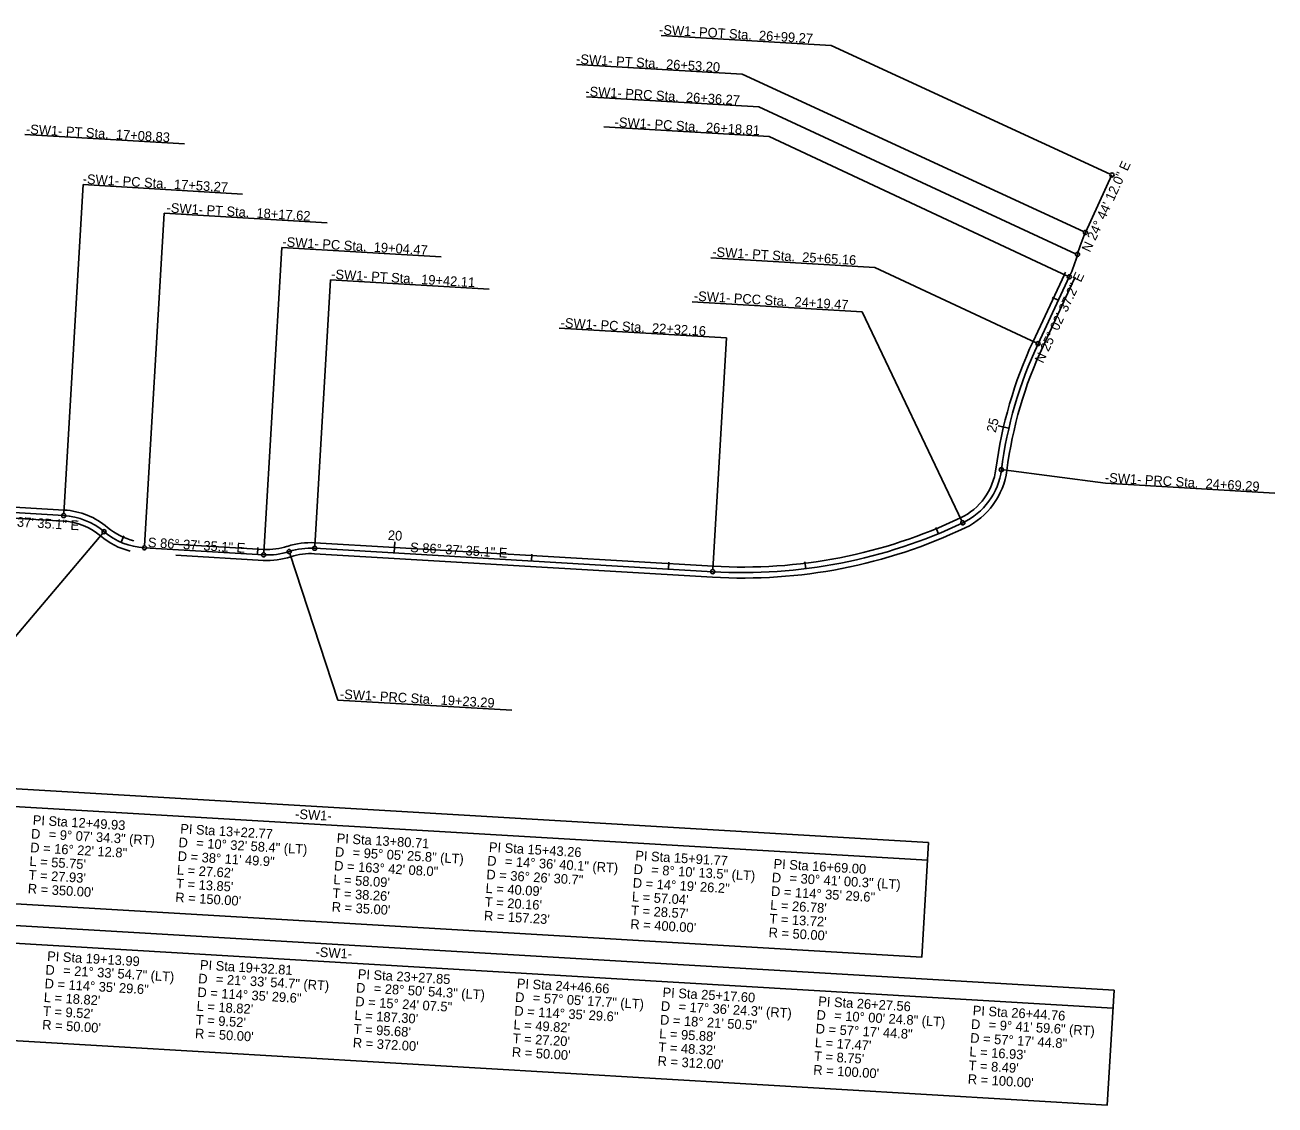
# Model space of a CAD drawing. Extents: x 2011926 to 2013370, y 444604 to 445429.
# Drawn here: x 2012461 to 2013370, y 444604 to 445390 of the extents above; entities that cross this region are included whole.
import ezdxf

# ---------------------------------------------------------------- set-up
doc = ezdxf.new("R2010")
doc.units = 0
for name, color, linetype in [('CTL Secondary Horizontal and Vertical CELL', 7, 'Continuous'), ('Exist Structure Minor Drop Inlet Cogo Number', 7, 'Continuous'), ('Exist Structure Minor Pipes RCP 18 Inch', 7, 'Continuous'), ('Exist Structure Minor Pipes RCP 18 Inch Cogo Point CELL', 7, 'Continuous'), ('Exist Structure Minor Pipes RCP 24 Inch Cogo Point CELL', 7, 'Continuous'), ('Exist Structure Minor Pipes RCP 36 Inch', 7, 'Continuous'), ('Exist Utilities Sanitary Sewer UG Line', 7, 'Continuous'), ('Exist Utilities Sanitary Sewer UG Line Cogo Number', 7, 'Continuous')]:
    doc.layers.add(name, color=color, linetype=linetype)

msp = doc.modelspace()

# ---------------------------------------------------------------- linework, layer by layer
at = {"layer": 'CTL Secondary Horizontal and Vertical CELL'}
for p, q in [((2013194.49, 445159.8), (2013217.2, 445208.4)), ((2013201.74, 445156.41), (2013224.44, 445205.01)), ((2012445.24, 445039.69), (2012489.6, 445037.07)), ((2012444.77, 445031.7), (2012489.13, 445029.09)), ((2012568.88, 445012.36), (2012635.02, 445008.47)), ((2012672.12, 445013.29), (2012961.67, 444996.22)), ((2012570.99, 445004.23), (2012634.55, 445000.48)), ((2012671.65, 445005.3), (2012961.2, 444988.24))]:
    msp.add_line(p, q, dxfattribs=at)
for centre, radius, start, end in [((2013130.22, 445249.04), 96, 334.95634, 336.07088), ((2013130.22, 445249.04), 104, 334.95634, 335.91649), ((2013480.78, 445026.04), 316, 154.95634, 172.56311), ((2013480.78, 445026.04), 308, 154.95634, 172.56311), ((2013121.83, 445072.89), 46, 295.47485, 352.56311), ((2013121.83, 445072.89), 54, 295.47485, 352.56311), ((2012486.42, 444983.17), 54, 49.75653, 86.62643), ((2012486.42, 444983.17), 54, 49.75653, 86.62643), ((2012486.42, 444983.17), 46, 49.75653, 86.62643), ((2012486.42, 444983.17), 46, 49.75653, 86.62643), ((2012551.03, 445059.5), 46, 229.75653, 256.57927), ((2012983.33, 445363.58), 376, 266.62643, 295.47485), ((2012983.33, 445363.58), 368, 266.62643, 295.47485), ((2012551.03, 445059.5), 54, 229.75653, 255.68879), ((2012637.72, 445054.39), 46, 266.62643, 288.19161), ((2012637.72, 445054.39), 46, 266.62643, 288.19161), ((2012668.94, 444959.38), 54, 86.62643, 108.19161), ((2012668.94, 444959.38), 54, 86.62643, 108.19161), ((2012637.72, 445054.39), 54, 266.62643, 288.19161), ((2012637.72, 445054.39), 54, 266.62643, 288.19161), ((2012668.94, 444959.38), 46, 86.62643, 108.19161), ((2012668.94, 444959.38), 46, 86.62643, 108.19161)]:
    msp.add_arc(centre, radius, start, end, dxfattribs=at)
at = {"layer": 'Exist Structure Minor Drop Inlet Cogo Number'}
for p, q in [((2013232.55, 445239), (2013251.83, 445280.84)), ((2013232.55, 445239), (2013251.83, 445280.84)), ((2013198.11, 445158.11), (2013220.82, 445206.71)), ((2013198.11, 445158.11), (2013220.82, 445206.71)), ((2012445, 445035.69), (2012489.36, 445033.08)), ((2012445, 445035.69), (2012489.36, 445033.08)), ((2012548.08, 445009.58), (2012634.78, 445004.47)), ((2012548.08, 445009.58), (2012634.78, 445004.47)), ((2012671.89, 445009.3), (2012961.44, 444992.23)), ((2012671.89, 445009.3), (2012961.44, 444992.23))]:
    msp.add_line(p, q, dxfattribs=at)
for centre, radius, start, end in [((2013323.37, 445197.15), 100, 155.26333, 164.96323), ((2013323.37, 445197.15), 100, 155.26333, 164.96323), ((2013130.22, 445249.04), 100, 334.95634, 344.96323), ((2013130.22, 445249.04), 100, 334.95634, 344.96323), ((2013480.78, 445026.04), 312, 154.95634, 172.56311), ((2013480.78, 445026.04), 312, 154.95634, 172.56311), ((2013121.83, 445072.89), 50, 295.47485, 352.56311), ((2013121.83, 445072.89), 50, 295.47485, 352.56311), ((2012486.42, 444983.17), 50, 49.75653, 86.62643), ((2012486.42, 444983.17), 50, 49.75653, 86.62643), ((2012983.33, 445363.58), 372, 266.62643, 295.47485), ((2012983.33, 445363.58), 372, 266.62643, 295.47485), ((2012551.03, 445059.5), 50, 229.75653, 266.62643), ((2012551.03, 445059.5), 50, 229.75653, 266.62643), ((2012637.72, 445054.39), 50, 266.62643, 288.19161), ((2012637.72, 445054.39), 50, 266.62643, 288.19161), ((2012668.94, 444959.38), 50, 86.62643, 108.19161), ((2012668.94, 444959.38), 50, 86.62643, 108.19161)]:
    msp.add_arc(centre, radius, start, end, dxfattribs=at)
at = {"layer": 'Exist Structure Minor Pipes RCP 18 Inch'}
for p, q in [((2013176.87, 445096.63), (2013169.08, 445098.44)), ((2012729.68, 445005.89), (2012730.15, 445013.88))]:
    msp.add_line(p, q, dxfattribs=at)
at = {"layer": 'Exist Structure Minor Pipes RCP 24 Inch Cogo Point CELL'}
for p, q in [((2013212.86, 445189.67), (2013208.33, 445191.79)), ((2013125.55, 445019.84), (2013123.63, 445024.46)), ((2012531.03, 445013.67), (2012533.03, 445018.25)), ((2012630.32, 445004.74), (2012630.61, 445009.73)), ((2012829.5, 445000.01), (2012829.8, 445005)), ((2012929.33, 444994.12), (2012929.62, 444999.11)), ((2013029.14, 444994.42), (2013028.53, 444999.38))]:
    msp.add_line(p, q, dxfattribs=at)
at = {"layer": 'Exist Utilities Sanitary Sewer UG Line'}
for p, q in [((2012235.82, 444834.24), (2013117.6, 444782.26)), ((2012135.32, 444740.69), (2013252.58, 444674.83))]:
    msp.add_line(p, q, dxfattribs=at)
for points in [[(2012236.58, 444847.2), (2013118.36, 444795.22), (2013113.44, 444711.71), (2012231.66, 444763.68)], [(2012136.08, 444753.64), (2013253.34, 444687.78), (2013248.42, 444604.27), (2012131.16, 444670.13)]]:
    msp.add_lwpolyline(points, close=True, dxfattribs=at)
at = {"layer": 'Exist Utilities Sanitary Sewer UG Line Cogo Number'}
for p, q in [((2013047.63, 445374.92), (2012923.97, 445382.21)), ((2013250.47, 445281.47), (2013047.63, 445374.92)), ((2012982.78, 445354.07), (2012862.25, 445361.17)), ((2013231.19, 445239.62), (2012982.78, 445354.07)), ((2012995.08, 445330.29), (2012869.59, 445337.68)), ((2013225.35, 445223.48), (2012995.08, 445330.29)), ((2013002.5, 445308.71), (2012882.17, 445315.81)), ((2012577.19, 445303.38), (2012461.18, 445310.22)), ((2013219.46, 445207.34), (2013002.5, 445308.71)), ((2012489.45, 445034.58), (2012503.55, 445273.8)), ((2012619.46, 445266.96), (2012503.55, 445273.8)), ((2012548.17, 445011.08), (2012562.44, 445253.06)), ((2012681.07, 445246.07), (2012562.44, 445253.06)), ((2012634.87, 445005.97), (2012647.96, 445228.01)), ((2012763.9, 445221.17), (2012647.96, 445228.01)), ((2013079.29, 445213.63), (2012960.01, 445220.66)), ((2013196.75, 445158.74), (2013079.29, 445213.63)), ((2012671.97, 445010.79), (2012683.4, 445204.62)), ((2012798.84, 445197.81), (2012683.4, 445204.62)), ((2013070.18, 445181.3), (2012946.52, 445188.59)), ((2013142.69, 445029.11), (2013070.18, 445181.3)), ((2012971.46, 445162.29), (2012849.69, 445169.47)), ((2012961.53, 444993.73), (2012971.46, 445162.29)), ((2013172.89, 445066.22), (2013247.07, 445056.54)), ((2013370.43, 445049.27), (2013247.07, 445056.54)), ((2012429.9, 444916.39), (2012517.75, 445020.19)), ((2012688.83, 444898.88), (2012653.8, 445005.46)), ((2012815.34, 444891.42), (2012688.83, 444898.88))]:
    msp.add_line(p, q, dxfattribs=at)
for centre in [(2013251.83, 445280.84), (2013232.55, 445239), (2013226.8, 445223.1), (2013220.82, 445206.71), (2013198.11, 445158.11), (2013171.4, 445066.42), (2012489.36, 445033.08), (2013143.33, 445027.75), (2012518.72, 445021.33), (2012548.08, 445009.58), (2012634.78, 445004.47), (2012653.33, 445006.88), (2012671.89, 445009.3), (2012961.44, 444992.23)]:
    msp.add_circle(centre, 1.5, dxfattribs=at)

# ---------------------------------------------------------------- texts
at = {"layer": 'Exist Structure Minor Pipes RCP 18 Inch Cogo Point CELL'}
for s, rotation, p in [('25', 76.9227, (2013167.3, 445093.02)), ('20', 356.62643, (2012724.99, 445015.38))]:
    msp.add_text(s, height=7, rotation=rotation, dxfattribs=at).set_placement(p)
at = {"layer": 'Exist Structure Minor Pipes RCP 36 Inch'}
for s, rotation, p in [('N 24%%d 44\' 12.0" E', 65.26333, (2013235.82, 445224.12)), ('N 25%%d 02\' 37.2" E', 64.95634, (2013201.69, 445143.38)), ('S 86%%d 37\' 35.1" E', 356.62643, (2012429.63, 445026.55)), ('S 86%%d 37\' 35.1" E', 356.62643, (2012550.44, 445010.14)), ('S 86%%d 37\' 35.1" E', 356.62643, (2012741.19, 445006.57))]:
    msp.add_text(s, height=7, rotation=rotation, dxfattribs=at).set_placement(p)
at = {"layer": 'Exist Utilities Sanitary Sewer UG Line'}
for s, p in [('PI Sta 12+49.93', (2012466.69, 444808.17)), ('-SW1-', (2012657.54, 444812.6)), ('PI Sta 13+22.77', (2012573.98, 444801.85)), ('D', (2012465.43, 444798.22)), ('= 9%%d 07\' 34.3" (RT)', (2012478.28, 444797.76)), ('D', (2012572.72, 444791.91)), ('= 10%%d 32\' 58.4" (LT)', (2012585.57, 444791.45)), ('PI Sta 13+80.71', (2012687.76, 444794.92)), ('D = 16%%d 22\' 12.8"', (2012464.84, 444788.24)), ('D = 38%%d 11\' 49.9"', (2012572.13, 444781.92)), ('D', (2012686.5, 444784.98)), ('= 95%%d 05\' 25.8" (LT)', (2012699.34, 444784.52)), ('PI Sta 15+43.26', (2012798.5, 444788.5)), ('PI Sta 15+91.77', (2012904.97, 444782.36)), ("L = 55.75'", (2012464.26, 444778.26)), ("L = 27.62'", (2012571.54, 444771.94)), ('D = 163%%d 42\' 08.0"', (2012685.91, 444775)), ('D', (2012797.24, 444778.56)), ('= 14%%d 36\' 40.1" (RT)', (2012810.09, 444778.1)), ('D', (2012903.71, 444772.42)), ('= 8%%d 10\' 13.5" (LT)', (2012916.55, 444771.96)), ('PI Sta 16+69.00', (2013005.54, 444776.32)), ("T = 27.93'", (2012463.67, 444768.27)), ("L = 58.09'", (2012685.32, 444765.01)), ('D = 36%%d 26\' 30.7"', (2012796.65, 444768.58)), ('D = 14%%d 19\' 26.2"', (2012903.12, 444762.44)), ('D', (2013004.28, 444766.37)), ('= 30%%d 41\' 00.3" (LT)', (2013017.13, 444765.91)), ("R = 350.00'", (2012463.08, 444758.29)), ("T = 13.85'", (2012570.96, 444761.96)), ("T = 38.26'", (2012684.73, 444755.03)), ("L = 40.09'", (2012796.06, 444758.59)), ('D = 114%%d 35\' 29.6"', (2013003.69, 444756.39)), ("R = 150.00'", (2012570.37, 444751.98)), ("R = 35.00'", (2012684.14, 444745.05)), ("T = 20.16'", (2012795.48, 444748.61)), ("L = 57.04'", (2012902.53, 444752.45)), ("L = 26.78'", (2013003.11, 444746.41)), ("R = 157.23'", (2012794.89, 444738.63)), ("T = 28.57'", (2012901.94, 444742.47)), ("T = 13.72'", (2013002.52, 444736.43)), ("R = 400.00'", (2012901.36, 444732.49)), ("R = 50.00'", (2013001.93, 444726.44)), ('PI Sta 19+13.99', (2012477.15, 444709.16)), ('-SW1-', (2012672.33, 444712.25)), ('D', (2012475.89, 444699.22)), ('PI Sta 19+32.81', (2012588.3, 444702.82)), ('= 21%%d 33\' 54.7" (LT)', (2012488.74, 444698.76)), ('D', (2012587.04, 444692.88)), ('= 21%%d 33\' 54.7" (RT)', (2012599.88, 444692.42)), ('PI Sta 23+27.85', (2012703.12, 444696.12)), ('D = 114%%d 35\' 29.6"', (2012475.3, 444689.24)), ('D = 114%%d 35\' 29.6"', (2012586.45, 444682.9)), ('D', (2012701.86, 444686.17)), ('= 28%%d 50\' 54.3" (LT)', (2012714.7, 444685.71)), ('PI Sta 24+46.66', (2012818.81, 444689.3)), ('PI Sta 25+17.60', (2012924.81, 444682.82)), ("L = 18.82'", (2012474.72, 444679.25)), ("L = 18.82'", (2012585.86, 444672.91)), ('D = 15%%d 24\' 07.5"', (2012701.27, 444676.19)), ('D', (2012817.54, 444679.36)), ('= 57%%d 05\' 17.7" (LT)', (2012830.39, 444678.9)), ('D', (2012923.55, 444672.88)), ('= 17%%d 36\' 24.3" (RT)', (2012936.39, 444672.42)), ('PI Sta 26+27.56', (2013038.04, 444676.34)), ("T = 9.52'", (2012474.13, 444669.27)), ("T = 9.52'", (2012585.27, 444662.93)), ("L = 187.30'", (2012700.68, 444666.21)), ('D = 114%%d 35\' 29.6"', (2012816.96, 444669.38)), ('D = 18%%d 21\' 50.5"', (2012922.96, 444662.9)), ('D', (2013036.78, 444666.4)), ('= 10%%d 00\' 24.8" (LT)', (2013049.62, 444665.94)), ('PI Sta 26+44.76', (2013150.42, 444669.62)), ("R = 50.00'", (2012473.54, 444659.29)), ("T = 95.68'", (2012700.09, 444656.23)), ("L = 49.82'", (2012816.37, 444659.39)), ('D = 57%%d 17\' 44.8"', (2013036.19, 444656.42)), ('D', (2013149.16, 444659.68)), ('= 9%%d 41\' 59.6" (RT)', (2013162, 444659.22)), ("R = 50.00'", (2012584.69, 444652.95)), ("R = 372.00'", (2012699.5, 444646.24)), ("T = 27.20'", (2012815.78, 444649.41)), ("L = 95.88'", (2012922.37, 444652.91)), ("L = 17.47'", (2013035.6, 444646.43)), ('D = 57%%d 17\' 44.8"', (2013148.57, 444649.69)), ("R = 50.00'", (2012815.19, 444639.43)), ("T = 48.32'", (2012921.78, 444642.93)), ("T = 8.75'", (2013035.01, 444636.45)), ("L = 16.93'", (2013147.98, 444639.71)), ("R = 312.00'", (2012921.2, 444632.95)), ("R = 100.00'", (2013034.43, 444626.47)), ("T = 8.49'", (2013147.39, 444629.73)), ("R = 100.00'", (2013146.8, 444619.75))]:
    msp.add_text(s, height=7, rotation=356.62643, dxfattribs=at).set_placement(p)
at = {"layer": 'Exist Utilities Sanitary Sewer UG Line Cogo Number'}
for s, p in [('-SW1- POT Sta.  26+99.27', (2012922.24, 445383.15)), ('-SW1- PT Sta.  26+53.20', (2012861.92, 445361.86)), ('-SW1- PRC Sta.  26+36.27', (2012868.6, 445338.33)), ('-SW1- PT Sta.  17+08.83', (2012461.73, 445310.8)), ('-SW1- PC Sta.  26+18.81', (2012889.9, 445315.98)), ('-SW1- PC Sta.  17+53.27', (2012502.97, 445274.57)), ('-SW1- PT Sta.  18+17.62', (2012563.99, 445253.63)), ('-SW1- PC Sta.  19+04.47', (2012648.24, 445228.84)), ('-SW1- PT Sta.  25+65.16', (2012960.94, 445221.52)), ('-SW1- PT Sta.  19+42.11', (2012683.77, 445205.32)), ('-SW1- PCC Sta.  24+19.47', (2012947.55, 445189.46)), ('-SW1- PC Sta.  22+32.16', (2012850.63, 445169.99)), ('-SW1- PRC Sta.  24+69.29', (2013246.56, 445057.29)), ('-SW1- PRC Sta.  19+23.29', (2012690.12, 444899.84))]:
    msp.add_text(s, height=7, rotation=356.62643, dxfattribs=at).set_placement(p)

doc.saveas('drawing.dxf')
